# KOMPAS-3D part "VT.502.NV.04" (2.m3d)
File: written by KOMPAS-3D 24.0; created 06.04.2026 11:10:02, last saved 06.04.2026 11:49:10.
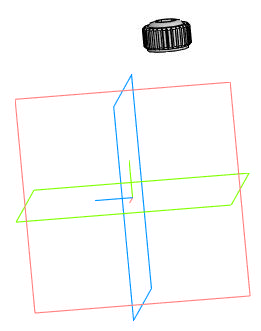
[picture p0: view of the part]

Document properties: Автор: R2D2; Полное имя файла: E:\Работа\Зайцев\Солянка\AV00E-T Воздухоотводчик DN.ru\Ду15 Ру10\исходные материалы\2.m3d

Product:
- Body: Твердое тело1  | qty 1
    Масса: 0.003903
- Part/product: VT.502.NV.04
    Масса: 0.003903
    additional columns: Типовые

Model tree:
1. Твердое тело1  (labels: Твердое тело1)
2. Эскиз:1  (labels: Грань.Твердое тело1)
3. Элемент выдавливания:1
     Расстояние 1 = 0.5
4. Эскиз:2  (labels: Грань.Твердое тело1; Ребро.Твердое тело1)
5. Элемент выдавливания:2
     Расстояние 1 = 0.5
6. Эскиз:3
7. Элемент выдавливания:3
     Расстояние 1 = 100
